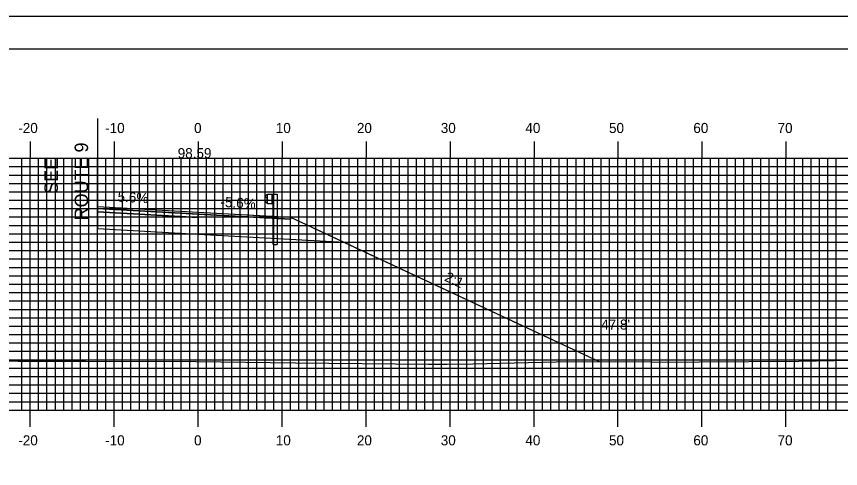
# Model space of a CAD drawing. Extents: x 2453 to 2796, y -1658 to -1438.
# Drawn here: x 2597.1 to 2695.2, y -1491.6 to -1437.7 of the extents above; entities that cross this region are included whole.
import ezdxf

# ---------------------------------------------------------------- set-up
doc = ezdxf.new("R2010")
doc.units = 0
for name, color, linetype in [('ANNOTATION', 7, 'Continuous'), ('BORDER', 7, 'Continuous'), ('D_Guardrail_Beam_Rt', 7, 'Continuous'), ('D_Roadway_Centerline', 7, 'Continuous'), ('D_Roadway_Centerline_Text', 7, 'Continuous'), ('D_Roadway_Edge_Shoulder', 7, 'Continuous'), ('D_Roadway_Edge_TW', 7, 'Continuous'), ('D_Roadway_Pavement', 7, 'Continuous'), ('D_Roadway_SlopeLines', 7, 'Continuous'), ('D_Roadway_SubGrade', 7, 'Continuous'), ('D_Text_Standard', 7, 'Continuous'), ('H_V ANNOTATION', 7, 'Continuous'), ('MAJOR', 7, 'Continuous'), ('MINOR', 7, 'Continuous'), ('PLOT BOUNDARY', 7, 'Continuous'), ('S_Roadway_Centerline', 7, 'Continuous')]:
    doc.layers.add(name, color=color, linetype=linetype)

msp = doc.modelspace()

# ---------------------------------------------------------------- linework, layer by layer
at = {"layer": 'BORDER'}
msp.add_lwpolyline([(2469.1, -1651.604), (2789.1, -1651.604), (2789.1, -1441.604), (2469.1, -1441.604)], close=True, dxfattribs=at)
at = {"layer": 'D_Guardrail_Beam_Rt'}
for p, q in [((2626.881, -1458.979), (2626.737, -1459.079)), ((2626.971, -1458.958), (2626.896, -1458.973)), ((2626.971, -1458.875), (2627.658, -1458.875)), ((2626.971, -1460.041), (2626.971, -1458.875)), ((2627.491, -1458.875), (2627.491, -1460.041)), ((2627.596, -1458.875), (2627.596, -1460.041)), ((2627.658, -1458.875), (2628.129, -1458.875)), ((2627.658, -1458.875), (2627.658, -1460.041)), ((2628.129, -1458.875), (2628.129, -1464.875)), ((2626.737, -1459.222), (2626.933, -1459.359)), ((2626.933, -1459.558), (2626.737, -1459.694)), ((2626.737, -1459.837), (2626.881, -1459.937)), ((2626.896, -1459.944), (2626.971, -1459.958)), ((2626.966, -1459.423), (2626.966, -1459.493)), ((2627.658, -1460.041), (2626.971, -1460.041)), ((2627.637, -1464.875), (2627.637, -1460.041)), ((2627.637, -1464.875), (2628.129, -1464.875))]:
    msp.add_line(p, q, dxfattribs=at)
for centre, major_axis, start_param, end_param in [((2626.788, -1459.151), (-0.0877, 0), 5.323254, 7.243116), ((2626.905, -1459.013), (-0.0417, 0), 4.907132, 5.323254), ((2626.788, -1459.765), (-0.0877, 0), 5.323254, 7.243116), ((2626.905, -1459.903), (-0.0417, 0), 0.959931, 1.376053), ((2626.887, -1459.423), (0.0789, 0), 0, 0.959931), ((2626.887, -1459.493), (0.0789, 0), 5.323254, 6.283185)]:
    msp.add_ellipse(centre, major_axis=major_axis, ratio=0.995501, start_param=start_param, end_param=end_param, dxfattribs=at)
at = {"layer": 'D_Roadway_Centerline'}
msp.add_lwpolyline([(2606.7, -1460.341), (2618.7, -1461.011), (2626.7, -1461.458), (2629.7, -1461.626), (2636.119, -1464.628), (2666.459, -1478.817)], dxfattribs=at)
at = {"layer": 'D_Roadway_Edge_Shoulder'}
for points in [[(2618.7, -1461.011), (2629.7, -1461.626), (2629.7, -1461.876), (2618.7, -1461.261)], [(2618.7, -1461.011), (2626.7, -1461.458), (2626.7, -1461.458), (2629.7, -1461.626), (2629.7, -1461.876), (2618.7, -1461.261)], [(2618.7, -1461.011), (2626.7, -1461.458), (2626.7, -1461.458), (2629.7, -1461.626), (2629.7, -1461.876), (2618.7, -1461.261)], [(2618.7, -1461.011), (2629.7, -1461.626), (2629.7, -1461.876), (2618.7, -1461.261)], [(2618.7, -1461.011), (2629.7, -1461.626), (2629.7, -1461.876), (2618.7, -1461.261)]]:
    msp.add_lwpolyline(points, close=True, dxfattribs=at)
at = {"layer": 'D_Roadway_Edge_TW'}
msp.add_lwpolyline([(2606.7, -1460.341), (2618.7, -1461.011), (2618.7, -1461.261), (2606.7, -1460.591)], close=True, dxfattribs=at)
msp.add_lwpolyline([(2606.7, -1460.341), (2618.7, -1461.011), (2618.7, -1461.261), (2606.7, -1460.591)], close=True, dxfattribs=at)
msp.add_lwpolyline([(2606.7, -1460.341), (2618.7, -1461.011), (2618.7, -1461.261), (2606.7, -1460.591)], close=True, dxfattribs=at)
msp.add_lwpolyline([(2606.7, -1460.341), (2618.7, -1461.011), (2618.7, -1461.261), (2606.7, -1460.591)], close=True, dxfattribs=at)
at = {"layer": 'D_Roadway_Pavement'}
msp.add_lwpolyline([(2606.7, -1460.591), (2618.7, -1461.261), (2618.7, -1461.678), (2606.7, -1461.007)], close=True, dxfattribs=at)
msp.add_lwpolyline([(2606.7, -1460.591), (2618.7, -1461.261), (2618.7, -1461.678), (2606.7, -1461.007)], close=True, dxfattribs=at)
msp.add_lwpolyline([(2606.7, -1460.591), (2618.7, -1461.261), (2618.7, -1461.678), (2606.7, -1461.007)], close=True, dxfattribs=at)
msp.add_lwpolyline([(2606.7, -1460.591), (2618.7, -1461.261), (2618.7, -1461.678), (2606.7, -1461.007)], close=True, dxfattribs=at)
msp.add_lwpolyline([(2618.7, -1461.261), (2618.7, -1461.678)], dxfattribs=at)
msp.add_lwpolyline([(2618.7, -1461.261), (2618.7, -1461.678)], dxfattribs=at)
msp.add_lwpolyline([(2618.7, -1461.261), (2618.7, -1461.678)], dxfattribs=at)
msp.add_lwpolyline([(2618.7, -1461.261), (2618.7, -1461.678)], dxfattribs=at)
msp.add_lwpolyline([(2618.7, -1461.261), (2618.7, -1461.678)], dxfattribs=at)
msp.add_lwpolyline([(2618.7, -1461.261), (2618.7, -1461.678)], dxfattribs=at)
msp.add_lwpolyline([(2618.7, -1461.261), (2618.7, -1461.678)], dxfattribs=at)
msp.add_lwpolyline([(2618.7, -1461.261), (2618.7, -1461.678)], dxfattribs=at)
msp.add_lwpolyline([(2618.7, -1461.261), (2618.7, -1461.678)], dxfattribs=at)
msp.add_lwpolyline([(2618.7, -1461.261), (2618.7, -1461.678)], dxfattribs=at)
msp.add_lwpolyline([(2618.7, -1461.261), (2618.7, -1461.678)], dxfattribs=at)
msp.add_lwpolyline([(2618.7, -1461.261), (2618.7, -1461.678)], dxfattribs=at)
msp.add_lwpolyline([(2618.7, -1461.261), (2618.7, -1461.678)], dxfattribs=at)
msp.add_lwpolyline([(2618.7, -1461.261), (2618.7, -1461.678)], dxfattribs=at)
at = {"layer": 'D_Roadway_SlopeLines'}
msp.add_lwpolyline([(2629.7, -1461.626), (2666.459, -1478.817)], dxfattribs=at)
msp.add_lwpolyline([(2629.7, -1461.626), (2666.459, -1478.817)], dxfattribs=at)
msp.add_lwpolyline([(2629.7, -1461.626), (2666.459, -1478.817)], dxfattribs=at)
msp.add_lwpolyline([(2629.7, -1461.626), (2666.459, -1478.817)], dxfattribs=at)
at = {"layer": 'D_Roadway_SubGrade'}
msp.add_line((2606.7, -1449.883), (2606.7, -1463.023), dxfattribs=at)
for points in [[(2606.7, -1461.007), (2618.7, -1461.678), (2618.7, -1463.678), (2606.7, -1463.023)], [(2606.7, -1461.007), (2618.7, -1461.678), (2618.7, -1463.678), (2606.7, -1463.023)], [(2606.7, -1461.007), (2618.7, -1461.678), (2618.7, -1463.678), (2606.7, -1463.023)], [(2606.7, -1461.007), (2618.7, -1461.678), (2618.7, -1463.678), (2606.7, -1463.023)], [(2618.7, -1461.678), (2618.7, -1461.261), (2629.7, -1461.876), (2629.7, -1461.626), (2636.119, -1464.628), (2618.7, -1463.678)]]:
    msp.add_lwpolyline(points, close=True, dxfattribs=at)
at = {"layer": 'MAJOR'}
for p, q in [((2598.7, -1452.6), (2598.7, -1454.604)), ((2608.7, -1452.6), (2608.7, -1454.604)), ((2618.7, -1452.6), (2618.7, -1454.604)), ((2628.7, -1452.6), (2628.7, -1454.604)), ((2638.7, -1452.6), (2638.7, -1454.604)), ((2648.7, -1452.6), (2648.7, -1454.604)), ((2658.7, -1452.6), (2658.7, -1454.604)), ((2668.7, -1452.6), (2668.7, -1454.604)), ((2678.7, -1452.6), (2678.7, -1454.604)), ((2688.7, -1452.6), (2688.7, -1454.604)), ((2478.7, -1454.604), (2758.7, -1454.604)), ((2478.7, -1454.604), (2758.7, -1454.604)), ((2598.7, -1484.604), (2598.7, -1454.604)), ((2608.7, -1484.604), (2608.7, -1454.604)), ((2618.7, -1484.604), (2618.7, -1454.604)), ((2628.7, -1484.604), (2628.7, -1454.604)), ((2638.7, -1484.604), (2638.7, -1454.604)), ((2648.7, -1484.604), (2648.7, -1454.604)), ((2658.7, -1484.604), (2658.7, -1454.604)), ((2668.7, -1484.604), (2668.7, -1454.604)), ((2678.7, -1484.604), (2678.7, -1454.604)), ((2688.7, -1484.604), (2688.7, -1454.604)), ((2478.7, -1459.604), (2758.7, -1459.604)), ((2478.7, -1464.604), (2758.7, -1464.604)), ((2478.7, -1469.604), (2758.7, -1469.604)), ((2478.7, -1474.604), (2758.7, -1474.604)), ((2478.7, -1479.604), (2758.7, -1479.604)), ((2478.7, -1484.604), (2758.7, -1484.604)), ((2478.7, -1484.604), (2758.7, -1484.604)), ((2598.7, -1486.608), (2598.7, -1484.604)), ((2608.7, -1486.608), (2608.7, -1484.604)), ((2618.7, -1486.608), (2618.7, -1484.604)), ((2628.7, -1486.608), (2628.7, -1484.604)), ((2638.7, -1486.608), (2638.7, -1484.604)), ((2648.7, -1486.608), (2648.7, -1484.604)), ((2658.7, -1486.608), (2658.7, -1484.604)), ((2668.7, -1486.608), (2668.7, -1484.604)), ((2678.7, -1486.608), (2678.7, -1484.604)), ((2688.7, -1486.608), (2688.7, -1484.604))]:
    msp.add_line(p, q, dxfattribs=at)
at = {"layer": 'MINOR'}
for p, q in [((2597.7, -1484.604), (2597.7, -1454.604)), ((2599.7, -1484.604), (2599.7, -1454.604)), ((2600.7, -1484.604), (2600.7, -1454.604)), ((2601.7, -1484.604), (2601.7, -1454.604)), ((2602.7, -1484.604), (2602.7, -1454.604)), ((2603.7, -1484.604), (2603.7, -1454.604)), ((2604.7, -1484.604), (2604.7, -1454.604)), ((2605.7, -1484.604), (2605.7, -1454.604)), ((2606.7, -1484.604), (2606.7, -1454.604)), ((2607.7, -1484.604), (2607.7, -1454.604)), ((2609.7, -1484.604), (2609.7, -1454.604)), ((2610.7, -1484.604), (2610.7, -1454.604)), ((2611.7, -1484.604), (2611.7, -1454.604)), ((2612.7, -1484.604), (2612.7, -1454.604)), ((2613.7, -1484.604), (2613.7, -1454.604)), ((2614.7, -1484.604), (2614.7, -1454.604)), ((2615.7, -1484.604), (2615.7, -1454.604)), ((2616.7, -1484.604), (2616.7, -1454.604)), ((2617.7, -1484.604), (2617.7, -1454.604)), ((2619.7, -1484.604), (2619.7, -1454.604)), ((2620.7, -1484.604), (2620.7, -1454.604)), ((2621.7, -1484.604), (2621.7, -1454.604)), ((2622.7, -1484.604), (2622.7, -1454.604)), ((2623.7, -1484.604), (2623.7, -1454.604)), ((2624.7, -1484.604), (2624.7, -1454.604)), ((2625.7, -1484.604), (2625.7, -1454.604)), ((2626.7, -1484.604), (2626.7, -1454.604)), ((2627.7, -1484.604), (2627.7, -1454.604)), ((2629.7, -1484.604), (2629.7, -1454.604)), ((2630.7, -1484.604), (2630.7, -1454.604)), ((2631.7, -1484.604), (2631.7, -1454.604)), ((2632.7, -1484.604), (2632.7, -1454.604)), ((2633.7, -1484.604), (2633.7, -1454.604)), ((2634.7, -1484.604), (2634.7, -1454.604)), ((2635.7, -1484.604), (2635.7, -1454.604)), ((2636.7, -1484.604), (2636.7, -1454.604)), ((2637.7, -1484.604), (2637.7, -1454.604)), ((2639.7, -1484.604), (2639.7, -1454.604)), ((2640.7, -1484.604), (2640.7, -1454.604)), ((2641.7, -1484.604), (2641.7, -1454.604)), ((2642.7, -1484.604), (2642.7, -1454.604)), ((2643.7, -1484.604), (2643.7, -1454.604)), ((2644.7, -1484.604), (2644.7, -1454.604)), ((2645.7, -1484.604), (2645.7, -1454.604)), ((2646.7, -1484.604), (2646.7, -1454.604)), ((2647.7, -1484.604), (2647.7, -1454.604)), ((2649.7, -1484.604), (2649.7, -1454.604)), ((2650.7, -1484.604), (2650.7, -1454.604)), ((2651.7, -1484.604), (2651.7, -1454.604)), ((2652.7, -1484.604), (2652.7, -1454.604)), ((2653.7, -1484.604), (2653.7, -1454.604)), ((2654.7, -1484.604), (2654.7, -1454.604)), ((2655.7, -1484.604), (2655.7, -1454.604)), ((2656.7, -1484.604), (2656.7, -1454.604)), ((2657.7, -1484.604), (2657.7, -1454.604)), ((2659.7, -1484.604), (2659.7, -1454.604)), ((2660.7, -1484.604), (2660.7, -1454.604)), ((2661.7, -1484.604), (2661.7, -1454.604)), ((2662.7, -1484.604), (2662.7, -1454.604)), ((2663.7, -1484.604), (2663.7, -1454.604)), ((2664.7, -1484.604), (2664.7, -1454.604)), ((2665.7, -1484.604), (2665.7, -1454.604)), ((2666.7, -1484.604), (2666.7, -1454.604)), ((2667.7, -1484.604), (2667.7, -1454.604)), ((2669.7, -1484.604), (2669.7, -1454.604)), ((2670.7, -1484.604), (2670.7, -1454.604)), ((2671.7, -1484.604), (2671.7, -1454.604)), ((2672.7, -1484.604), (2672.7, -1454.604)), ((2673.7, -1484.604), (2673.7, -1454.604)), ((2674.7, -1484.604), (2674.7, -1454.604)), ((2675.7, -1484.604), (2675.7, -1454.604)), ((2676.7, -1484.604), (2676.7, -1454.604)), ((2677.7, -1484.604), (2677.7, -1454.604)), ((2679.7, -1484.604), (2679.7, -1454.604)), ((2680.7, -1484.604), (2680.7, -1454.604)), ((2681.7, -1484.604), (2681.7, -1454.604)), ((2682.7, -1484.604), (2682.7, -1454.604)), ((2683.7, -1484.604), (2683.7, -1454.604)), ((2684.7, -1484.604), (2684.7, -1454.604)), ((2685.7, -1484.604), (2685.7, -1454.604)), ((2686.7, -1484.604), (2686.7, -1454.604)), ((2687.7, -1484.604), (2687.7, -1454.604)), ((2689.7, -1484.604), (2689.7, -1454.604)), ((2690.7, -1484.604), (2690.7, -1454.604)), ((2691.7, -1484.604), (2691.7, -1454.604)), ((2692.7, -1484.604), (2692.7, -1454.604)), ((2693.7, -1484.604), (2693.7, -1454.604)), ((2694.7, -1484.604), (2694.7, -1454.604)), ((2478.7, -1455.604), (2758.7, -1455.604)), ((2478.7, -1456.604), (2758.7, -1456.604)), ((2478.7, -1457.604), (2758.7, -1457.604)), ((2478.7, -1458.604), (2758.7, -1458.604)), ((2478.7, -1460.604), (2758.7, -1460.604)), ((2478.7, -1461.604), (2758.7, -1461.604)), ((2478.7, -1462.604), (2758.7, -1462.604)), ((2478.7, -1463.604), (2758.7, -1463.604)), ((2478.7, -1465.604), (2758.7, -1465.604)), ((2478.7, -1466.604), (2758.7, -1466.604)), ((2478.7, -1467.604), (2758.7, -1467.604)), ((2478.7, -1468.604), (2758.7, -1468.604)), ((2478.7, -1470.604), (2758.7, -1470.604)), ((2478.7, -1471.604), (2758.7, -1471.604)), ((2478.7, -1472.604), (2758.7, -1472.604)), ((2478.7, -1473.604), (2758.7, -1473.604)), ((2478.7, -1475.604), (2758.7, -1475.604)), ((2478.7, -1476.604), (2758.7, -1476.604)), ((2478.7, -1477.604), (2758.7, -1477.604)), ((2478.7, -1478.604), (2758.7, -1478.604)), ((2478.7, -1480.604), (2758.7, -1480.604)), ((2478.7, -1481.604), (2758.7, -1481.604)), ((2478.7, -1482.604), (2758.7, -1482.604)), ((2478.7, -1483.604), (2758.7, -1483.604))]:
    msp.add_line(p, q, dxfattribs=at)
at = {"layer": 'PLOT BOUNDARY'}
msp.add_lwpolyline([(2452.913, -1657.723), (2792.913, -1657.723), (2792.913, -1437.723), (2452.913, -1437.723)], close=True, dxfattribs=at)
at = {"layer": 'S_Roadway_Centerline'}
msp.add_lwpolyline([(2588.65, -1478.671), (2597.268, -1478.768), (2605.306, -1478.776), (2618.436, -1478.808), (2630.281, -1478.96), (2646.119, -1479.147), (2648.343, -1479.116), (2651.394, -1479.075), (2661.355, -1478.862), (2668.356, -1478.8), (2676.918, -1478.879), (2678.352, -1478.853), (2690.234, -1478.769), (2707.162, -1478.463)], dxfattribs=at)

# ---------------------------------------------------------------- texts
at = {"layer": 'ANNOTATION'}
for s, height, rotation, p in [('ROUTE 9', 1.6, 90, (2605.595, -1462.005)), ('SEE', 1.6, 90, (2601.995, -1458.856)), ('5.6%', 1.2, 356.80221, (2609.084, -1459.768)), ('-5.6%', 1.2, 356.80227, (2621.338, -1460.393)), ('2:1', 1.2, 334.93582, (2647.954, -1469.155))]:
    msp.add_text(s, height=height, rotation=rotation, dxfattribs=at).set_placement(p)
at = {"layer": 'D_Roadway_Centerline_Text'}
msp.add_text('98.59', height=1.2, dxfattribs=at).set_placement((2616.27, -1454.602))
at = {"layer": 'D_Text_Standard'}
msp.add_text("47.8'", height=1.2, dxfattribs=at).set_placement((2666.698, -1475.021))
at = {"layer": 'H_V ANNOTATION'}
for s, p in [('-20', (2597.287, -1451.604)), ('-10', (2607.63, -1451.604)), ('0', (2618.218, -1451.604)), ('10', (2627.95, -1451.604)), ('20', (2637.608, -1451.604)), ('30', (2647.597, -1451.604)), ('40', (2657.672, -1451.604)), ('50', (2667.629, -1451.604)), ('60', (2677.672, -1451.604)), ('70', (2687.704, -1451.604)), ('-20', (2597.287, -1488.804)), ('-10', (2607.63, -1488.804)), ('0', (2618.218, -1488.804)), ('10', (2627.95, -1488.804)), ('20', (2637.608, -1488.804)), ('30', (2647.597, -1488.804)), ('40', (2657.672, -1488.804)), ('50', (2667.629, -1488.804)), ('60', (2677.672, -1488.804)), ('70', (2687.704, -1488.804))]:
    msp.add_text(s, height=1.2, dxfattribs=at).set_placement(p)

doc.saveas('drawing.dxf')
